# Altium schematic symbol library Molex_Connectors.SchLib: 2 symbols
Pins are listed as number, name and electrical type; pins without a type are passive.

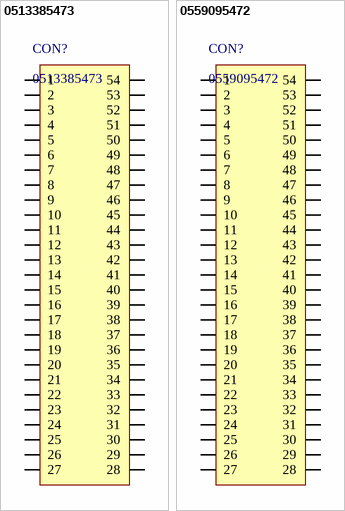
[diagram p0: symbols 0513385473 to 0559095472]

## 0513385473
designator CON?
0513385473 Female Connector
footprint 0513385473 (Molex 052338 Series Connector - 54 pin)
pins: 1, 2, 3, 4, 5, 6, 7, 8, 9, 10, 11, 12, 13, 14, 15, 16, 17, 18, 19, 20, 21, 22, 23, 24, 25, 26, 27, 28, 29, 30, 31, 32, 33, 34, 35, 36, 37, 38, 39, 40, 41, 42, 43, 44, 45, 46, 47, 48, 49, 50, 51, 52, 53, 54

## 0559095472
designator CON?
0559095472 Male Connector
footprint 0559095472 (Molex 055909 Series Connector - 54 pin)
pins: 1, 2, 3, 4, 5, 6, 7, 8, 9, 10, 11, 12, 13, 14, 15, 16, 17, 18, 19, 20, 21, 22, 23, 24, 25, 26, 27, 28, 29, 30, 31, 32, 33, 34, 35, 36, 37, 38, 39, 40, 41, 42, 43, 44, 45, 46, 47, 48, 49, 50, 51, 52, 53, 54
